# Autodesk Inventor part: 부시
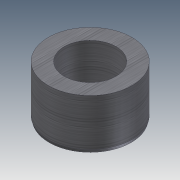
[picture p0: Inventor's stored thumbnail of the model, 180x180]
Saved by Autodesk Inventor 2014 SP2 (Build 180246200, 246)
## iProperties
Company: 한국ATC센터
Created: 2014-11
Part Number: 부시
Document SubType Name: Modeling
Designer: KYOUNG IL JANG
Density: 7.86 g/cm^3
Material: 강, 연강
Mass: 167.601 g
Surface Area: 70.0223 cm^2
Volume: 21.3233 cm^3
Appearance: 금속-강(기계 가공_02)
Author: KYOUNG IL JANG
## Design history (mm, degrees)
sketch "스케치1"
  geometry: C1 r 21 at (0, 0); C2 r 13 at (0, 0); 1 further point
  constraints: 2 centre point, 2 coincident
  dimensions: "d4" = 26 diameter of C2; "d5" = 42 diameter of C1
extrude "돌출1" new body sketch "스케치1" distance "d0" = 25; taper "d1" = 0 deg
chamfer "모따기1" distance "d6" = 1.5; stored, may be unused: second distance "d7" = 2, angle "d8" = 15 deg
node "솔리드1"
